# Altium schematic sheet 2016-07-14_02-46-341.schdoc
size 331 x 127 mm; SheetNumber: 1; SheetTotal: 1
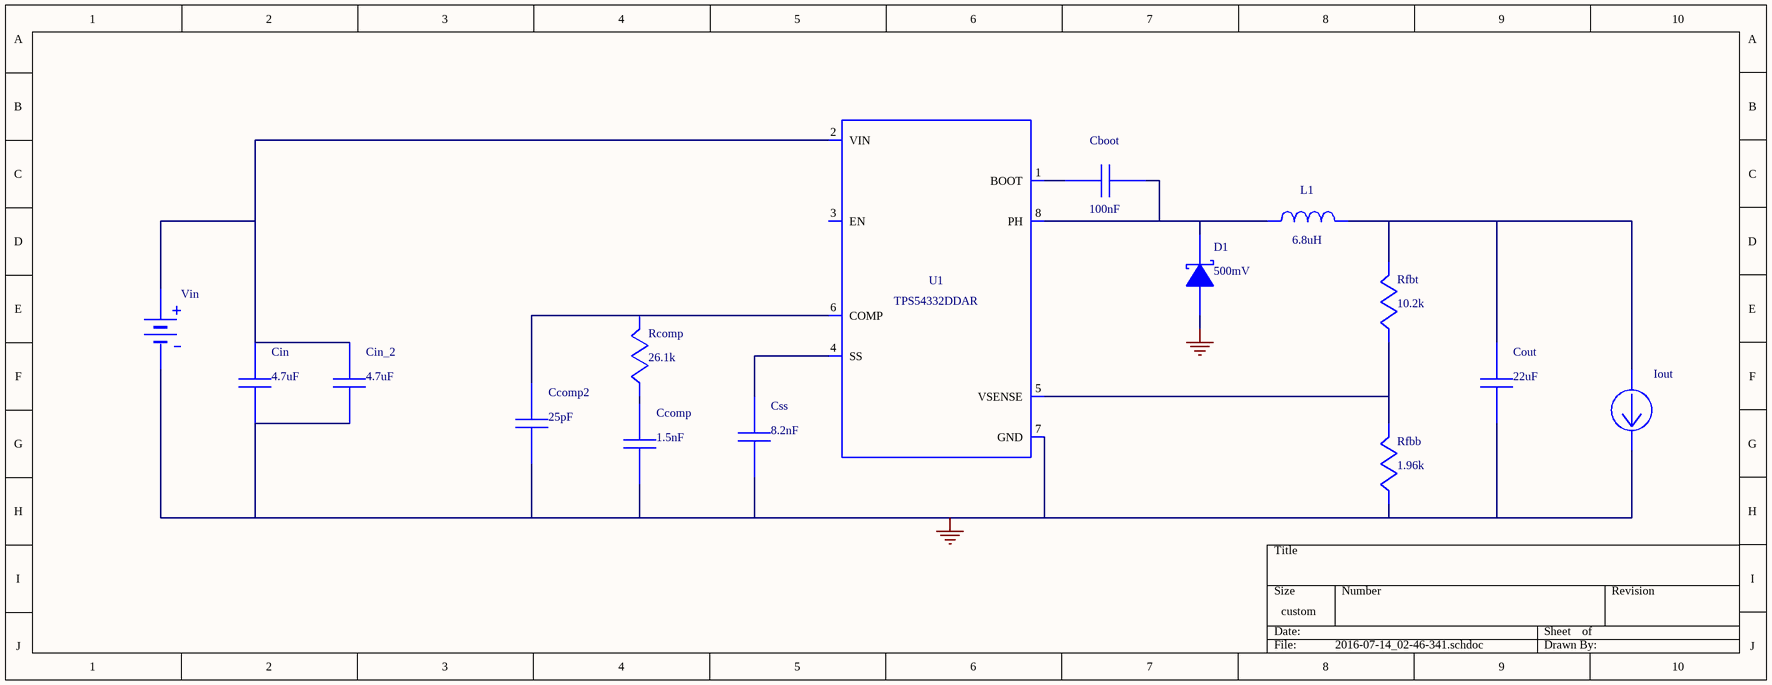
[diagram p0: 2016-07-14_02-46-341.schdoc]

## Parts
Cboot  value 100nF  (hidden comment: GRM155R61A104KA01D)
Ccomp  value 1.5nF  (hidden comment: CC0805KRX7R9BB152)
Ccomp2  value 25pF  (hidden comment: CL21C250JBANNNC)
Cin  value 4.7uF  (hidden comment: GRM32ER71H475KA88L)
Cin_2  value 4.7uF  (hidden comment: GRM32ER71H475KA88L)
Cout  value 22uF  (hidden comment: GRM31CR61A226KE19L)
Css  value 8.2nF  (hidden comment: GRM033R61A822KA01D)
D1  value 500mV  (hidden comment: B340A-13-F)
Iout  WB_CURRENT_LOAD  (value not drawn)
L1  value 6.8uH  (hidden comment: SDR0805-6R8ML)
Rcomp  value 26.1k  (hidden comment: CRCW040226K1FKED)
Rfbb  value 1.96k  (hidden comment: CRCW04021K96FKED)
Rfbt  value 10.2k  (hidden comment: CRCW040210K2FKED)
U1  TPS54332DDAR
Vin  WB_BATTERY  (value not drawn)

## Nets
0: Ccomp.2 Ccomp2.2 Cin.2 Cin_2.2 Cout.2 Css.2 D1.2(A) Iout.2(-) Rfbb.2 U1.7(GND) U1.9(ETPAD) Vin.2(-)
NetCboot_1: Cboot.1 U1.1(BOOT)
NetCboot_2: Cboot.2 D1.1(K) L1.2 U1.8(PH)
NetCcomp2_1: Ccomp2.1 Rcomp.1 U1.6(COMP)
NetCcomp_1: Ccomp.1 Rcomp.2
NetCin_1: Cin.1 Cin_2.1 U1.2(VIN) Vin.1(+)
NetCout_1: Cout.1 Iout.1(+) L1.1 Rfbt.1
NetCss_1: Css.1 U1.4(SS)
NetRfbb_1: Rfbb.1 Rfbt.2 U1.5(VSENSE)

Not connected (* = marked no-connect by the designer): U1 3(EN)

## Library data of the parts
Cboot = GRM155R61A104KA01D: GRM155R61A104KA0; Manufacturer Name: MuRata
Ccomp = CC0805KRX7R9BB152: CC0805KRX7R9BB15; Manufacturer Name: Yageo America
Ccomp2 = CL21C250JBANNNC: Manufacturer Name: Samsung Electro-Mechanics
Cin Cin_2 = GRM32ER71H475KA88L: GRM32ER71H475KA8; Manufacturer Name: MuRata
Cout = GRM31CR61A226KE19L: GRM31CR61A226KE1; Manufacturer Name: MuRata
Css = GRM033R61A822KA01D: GRM033R61A822KA0; Manufacturer Name: MuRata
D1 = B340A-13-F: Manufacturer Name: Diodes Inc.
L1 = SDR0805-6R8ML: Manufacturer Name: Bourns
Rcomp = CRCW040226K1FKED: Manufacturer Name: Vishay-Dale
Rfbb = CRCW04021K96FKED: Manufacturer Name: Vishay-Dale
Rfbt = CRCW040210K2FKED: Manufacturer Name: Vishay-Dale
U1 = TPS54332DDAR: Manufacturer Name: Texas Instruments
